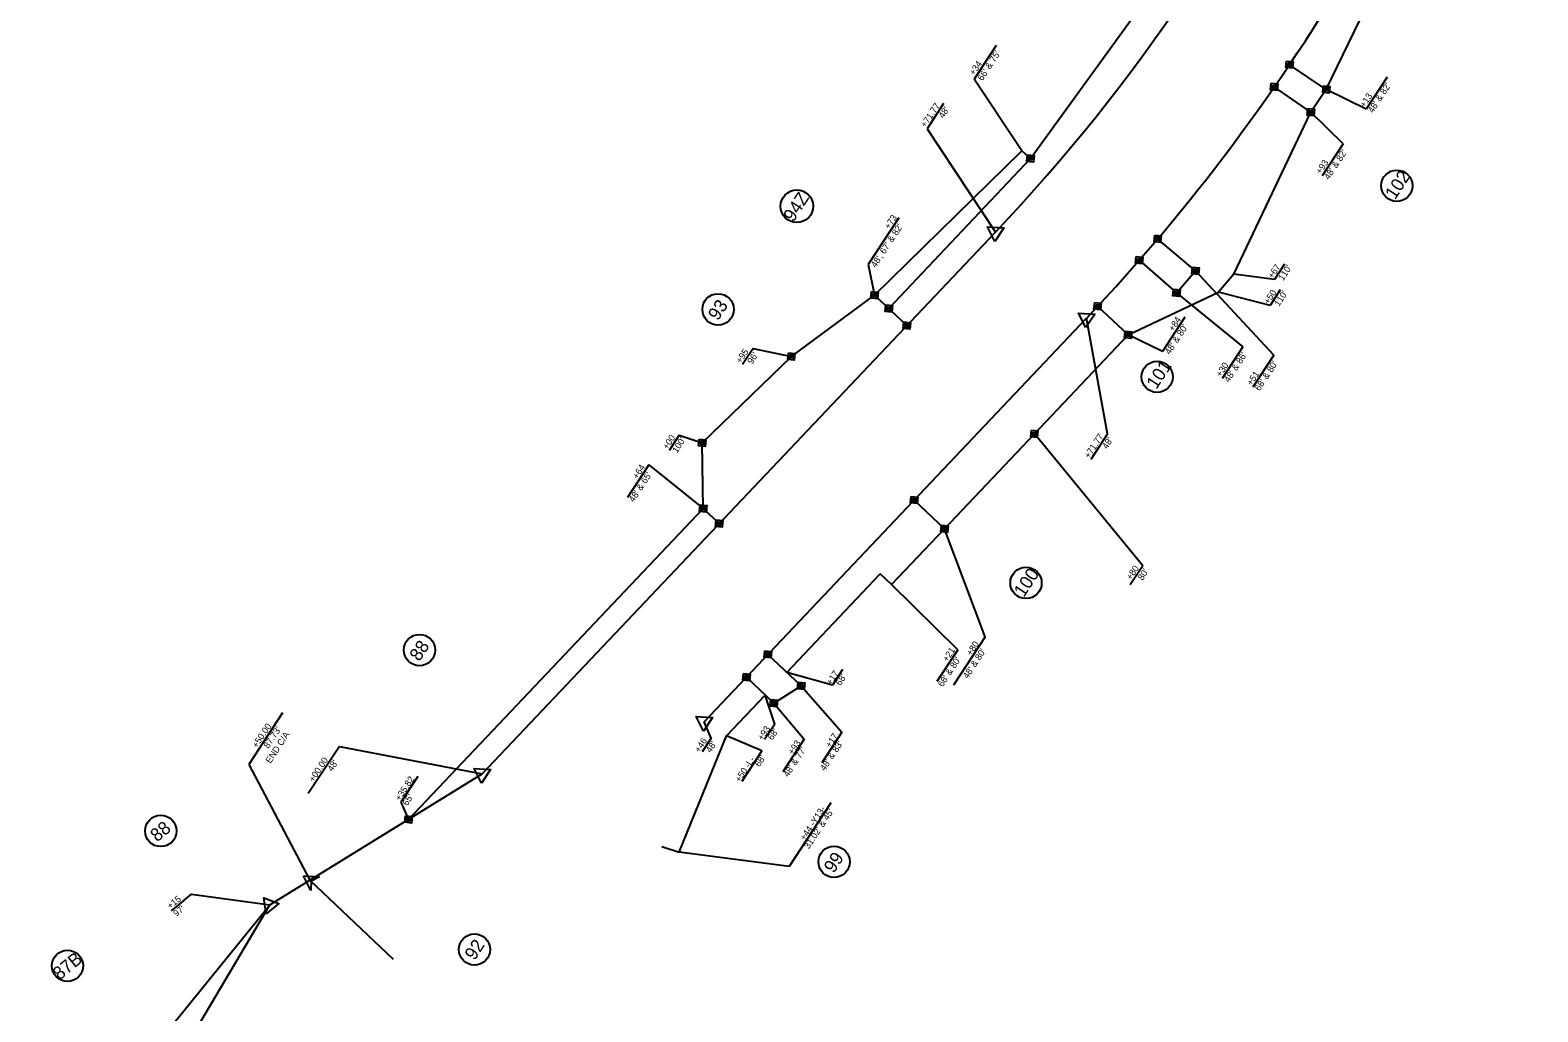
# Model space of a CAD drawing. Extents: x 2320946 to 2332748, y 597838 to 612698.
# Drawn here: x 2327264 to 2328420, y 602867 to 603619 of the extents above; entities that cross this region are included whole.
import ezdxf

# ---------------------------------------------------------------- set-up
doc = ezdxf.new("R2010")
doc.units = 0
for name, color, linetype in [('Prop Easement Construction', 7, 'Continuous'), ('Prop Easement Construction Station Offsets', 7, 'Continuous'), ('Prop Easement Permanent Drainage', 7, 'Continuous'), ('Prop Easement Permanent Drainage Station Offsets', 7, 'Continuous'), ('Prop Easement Permanent Drainage Utility', 7, 'Continuous'), ('Prop Easement Permanent Utility', 7, 'Continuous'), ('Prop Easement Permanent Utility Station Offsets', 7, 'Continuous'), ('Prop Parcel Number CELL', 7, 'Continuous'), ('Prop ROW CA Lines', 7, 'Continuous'), ('Prop ROW Marker CELL', 7, 'Continuous'), ('Prop ROW Permanent Easement CELL', 7, 'Continuous'), ('Prop ROW RW CA Lines', 7, 'Continuous'), ('Prop ROW RW Lines', 7, 'Continuous'), ('Prop ROW Station Offsets', 7, 'Continuous')]:
    doc.layers.add(name, color=color, linetype=linetype)

msp = doc.modelspace()

# ---------------------------------------------------------------- linework, layer by layer
at = {"layer": 'Prop Easement Construction'}
for p, q in [((2328257.6, 603573.9), (2328309.4, 603680.4)), ((2328186.8, 603432.5), (2328245.7, 603556.4)), ((2327911.5, 603416.4), (2328024.2, 603526.9)), ((2328024.2, 603526.9), (2328031, 603521)), ((2328186.8, 603432.5), (2328175, 603418.5)), ((2328105.8, 603386), (2328175, 603418.5)), ((2327924.5, 603194.6), (2327965.1, 603237.4)), ((2327844.2, 603127.4), (2327915.8, 603202.9)), ((2327924.5, 603194.6), (2327915.8, 603202.9)), ((2327798.1, 603078.8), (2327827.7, 603110)), ((2327761.6, 602989.6), (2327798.1, 603078.8)), ((2327748.3, 602994), (2327761.6, 602989.6)), ((2327264.3, 602723.6), (2327447.9, 602949.2))]:
    msp.add_line(p, q, dxfattribs=at)
at = {"layer": 'Prop Easement Construction Station Offsets'}
for p, q in [((2328004.7, 603607.6), (2327987.8, 603581.8)), ((2328024.2, 603526.9), (2327987.8, 603581.8)), ((2328225.7, 603440), (2328217.9, 603428.2)), ((2328222.4, 603420.3), (2328214.7, 603408.5)), ((2327975.2, 603144.7), (2327924.5, 603194.6)), ((2327975.2, 603144.7), (2327959.1, 603120.3)), ((2327879.2, 603117.7), (2327844.2, 603127.4)), ((2327887, 603129.6), (2327879.2, 603117.7)), ((2327834.9, 603087.7), (2327827.7, 603110)), ((2327834.9, 603087.7), (2327827.1, 603075.9)), ((2327825.1, 603067.3), (2327798.1, 603078.8)), ((2327825.1, 603067.3), (2327809.7, 603043.9)), ((2327878, 603027.5), (2327846, 602978.8)), ((2327846, 602978.8), (2327761.6, 602989.6))]:
    msp.add_line(p, q, dxfattribs=at)
for points in [[(2328217.9, 603428.2), (2328186.8, 603432.5)], [(2328214.7, 603408.5), (2328175, 603418.5)]]:
    msp.add_lwpolyline(points, dxfattribs=at)
at = {"layer": 'Prop Easement Permanent Drainage'}
for p, q in [((2328105.8, 603386), (2328082.4, 603407.8)), ((2328033.9, 603310), (2328105.8, 603386)), ((2327965.1, 603237.4), (2328033.9, 603310)), ((2327965.1, 603237.4), (2327941.8, 603259.4))]:
    msp.add_line(p, q, dxfattribs=at)
at = {"layer": 'Prop Easement Permanent Drainage Station Offsets'}
for p, q in [((2327930.1, 603475.6), (2327906.5, 603439.8)), ((2327906.5, 603439.8), (2327911.5, 603416.4)), ((2328149.3, 603399.4), (2328132, 603373.1)), ((2328132, 603373.1), (2328105.8, 603386)), ((2327817.9, 603374.8), (2327810.2, 603363.1)), ((2327761.8, 603309), (2327754, 603297.2)), ((2328117.1, 603209), (2328033.9, 603310)), ((2327738.5, 603286.3), (2327722.1, 603261.4)), ((2327738.5, 603286.3), (2327780, 603253)), ((2327996.1, 603154.5), (2327965.1, 603237.4)), ((2328117.1, 603209), (2328107.4, 603194.3)), ((2327996.1, 603154.5), (2327971.9, 603117.6))]:
    msp.add_line(p, q, dxfattribs=at)
for points in [[(2327817.9, 603374.8), (2327818.3, 603375.5), (2327847.7, 603369.4)], [(2327761.8, 603309), (2327779.4, 603303.2)]]:
    msp.add_lwpolyline(points, dxfattribs=at)
at = {"layer": 'Prop Easement Permanent Drainage Utility'}
for p, q in [((2328031, 603521), (2328123.8, 603649.1)), ((2327922.4, 603406), (2328031, 603521)), ((2327847.7, 603369.4), (2327911.5, 603416.4)), ((2327911.5, 603416.4), (2327936.2, 603393)), ((2327779.4, 603303.2), (2327847.7, 603369.4)), ((2327780, 603253), (2327779.4, 603303.2)), ((2327780, 603253), (2327792.4, 603241.3))]:
    msp.add_line(p, q, dxfattribs=at)
at = {"layer": 'Prop Easement Permanent Utility'}
for p, q in [((2328257.6, 603573.9), (2328229.4, 603592.8)), ((2328245.7, 603556.4), (2328217.8, 603575.8)), ((2328257.6, 603573.9), (2328245.7, 603556.4)), ((2328157.4, 603434.9), (2328128.4, 603459.5)), ((2328114.3, 603443.1), (2328142.9, 603418.1)), ((2328142.9, 603418.1), (2328157.4, 603434.9)), ((2327554.2, 603014.8), (2327780, 603253)), ((2327855.1, 603117.1), (2327829.7, 603141.1)), ((2327834.2, 603103.8), (2327813.2, 603123.7)), ((2327834.2, 603103.8), (2327855.1, 603117.1))]:
    msp.add_line(p, q, dxfattribs=at)
at = {"layer": 'Prop Easement Permanent Utility Station Offsets'}
for p, q in [((2328304.2, 603583.3), (2328288.1, 603558.8)), ((2328288.1, 603558.8), (2328257.6, 603573.9)), ((2328270.6, 603532.3), (2328245.7, 603556.4)), ((2328270.6, 603532.3), (2328254.5, 603507.8)), ((2328217.5, 603370.4), (2328157.4, 603434.9)), ((2328142.9, 603418.1), (2328193.7, 603376.6)), ((2328193.7, 603376.6), (2328177.8, 603352.5)), ((2328217.5, 603370.4), (2328201.4, 603345.9)), ((2327855.1, 603117.1), (2327886.4, 603081.5)), ((2327834.2, 603103.8), (2327857.6, 603076.1)), ((2327857.6, 603076.1), (2327841.2, 603051.1)), ((2327886.4, 603081.5), (2327871, 603058.1)), ((2327561.5, 603047.7), (2327548.5, 603028))]:
    msp.add_line(p, q, dxfattribs=at)
msp.add_lwpolyline([(2327548.5, 603028), (2327554.2, 603014.8)], dxfattribs=at)
at = {"layer": 'Prop Parcel Number CELL'}
for p, q in [((2328311.7, 603500.1), (2328311.7, 603500.1)), ((2327851.9, 603484.4), (2327851.9, 603484.4)), ((2327791.5, 603405.4), (2327791.5, 603405.4)), ((2328128, 603353.7), (2328128, 603353.7)), ((2328027.5, 603195.9), (2328027.5, 603195.9)), ((2327562.7, 603144.5), (2327562.7, 603144.5)), ((2327364.4, 603005.9), (2327364.4, 603005.9)), ((2327880.4, 602982.3), (2327880.4, 602982.3)), ((2327604.8, 602915.1), (2327604.8, 602915.1)), ((2327292.9, 602902.6), (2327292.9, 602902.6))]:
    msp.add_line(p, q, dxfattribs=at)
for centre, radius in [((2328311.7, 603500.1), 12), ((2327851.9, 603484.4), 12.5), ((2327791.5, 603405.4), 12), ((2328128, 603353.7), 12), ((2328027.5, 603195.9), 12), ((2327562.7, 603144.5), 12), ((2327364.4, 603005.9), 12), ((2327880.4, 602982.3), 12), ((2327604.8, 602915.1), 12), ((2327292.9, 602902.6), 12)]:
    msp.add_circle(centre, radius, dxfattribs=at)
at = {"layer": 'Prop ROW CA Lines'}
msp.add_line((2327478.7, 602968.2), (2327542.4, 602907.8), dxfattribs=at)
at = {"layer": 'Prop ROW Marker CELL'}
for p, q in [((2328229.4, 603592.8), (2328229.4, 603592.8)), ((2328217.8, 603575.8), (2328217.8, 603575.8)), ((2328257.6, 603573.9), (2328257.6, 603573.9)), ((2328245.7, 603556.4), (2328245.7, 603556.4)), ((2328031, 603521), (2328031, 603521)), ((2328004.1, 603464.6), (2328004.1, 603464.6)), ((2328128.4, 603459.5), (2328128.4, 603459.5)), ((2328114.3, 603443.1), (2328114.3, 603443.1)), ((2328157.4, 603434.9), (2328157.4, 603434.9)), ((2327911.5, 603416.4), (2327911.5, 603416.4)), ((2328142.9, 603418.1), (2328142.9, 603418.1)), ((2327922.4, 603406), (2327922.4, 603406)), ((2328073.8, 603398.6), (2328073.8, 603398.6)), ((2328082.4, 603407.8), (2328082.4, 603407.8)), ((2327936.2, 603393), (2327936.2, 603393)), ((2328105.8, 603386), (2328105.8, 603386)), ((2327847.7, 603369.4), (2327847.7, 603369.4)), ((2328033.9, 603310), (2328033.9, 603310)), ((2327779.4, 603303.2), (2327779.4, 603303.2)), ((2327941.8, 603259.4), (2327941.8, 603259.4)), ((2327780, 603253), (2327780, 603253)), ((2327792.4, 603241.3), (2327792.4, 603241.3)), ((2327965.1, 603237.4), (2327965.1, 603237.4)), ((2327829.7, 603141.1), (2327829.7, 603141.1)), ((2327813.2, 603123.7), (2327813.2, 603123.7)), ((2327855.1, 603117.1), (2327855.1, 603117.1)), ((2327834.2, 603103.8), (2327834.2, 603103.8)), ((2327780.8, 603089.6), (2327780.8, 603089.6)), ((2327610.7, 603049.7), (2327610.7, 603049.7)), ((2327554.2, 603014.8), (2327554.2, 603014.8)), ((2327479.3, 602960.3), (2327473.7, 602971.5)), ((2327473.7, 602971.5), (2327486.1, 602970.8)), ((2327486.1, 602970.8), (2327479.7, 602967.5)), ((2327479.7, 602967.5), (2327479.3, 602960.3)), ((2327447.9, 602949.2), (2327447.9, 602949.2))]:
    msp.add_line(p, q, dxfattribs=at)
for points in [[(2328003.7, 603457.4), (2327998.1, 603468.6), (2328010.6, 603467.9)], [(2328073.3, 603391.4), (2328067.8, 603402.6), (2328080.2, 603401.8)], [(2327780.4, 603082.4), (2327774.8, 603093.6), (2327787.3, 603092.9)], [(2327610.3, 603042.5), (2327604.7, 603053.7), (2327617.2, 603053)], [(2327445.3, 602942.4), (2327443.3, 602954.8), (2327455, 602950.3)]]:
    msp.add_lwpolyline(points, close=True, dxfattribs=at)
at = {"layer": 'Prop ROW Permanent Easement CELL'}
for points in [[(2328227.2, 603595.6), (2328232.2, 603595.1), (2328231.7, 603590.1), (2328226.7, 603590.6)], [(2328228.3, 603594.2), (2328230.8, 603594), (2328230.6, 603591.4), (2328228, 603591.7)], [(2328215.5, 603578.6), (2328220.6, 603578.1), (2328220.1, 603573), (2328215, 603573.5)], [(2328216.6, 603577.2), (2328219.2, 603576.9), (2328218.9, 603574.4), (2328216.4, 603574.6)], [(2328255.4, 603576.6), (2328260.4, 603576.1), (2328259.9, 603571.1), (2328254.9, 603571.6)], [(2328256.5, 603575.3), (2328259, 603575), (2328258.8, 603572.5), (2328256.3, 603572.7)], [(2328243.5, 603559.2), (2328248.5, 603558.7), (2328248, 603553.6), (2328242.9, 603554.1)], [(2328244.6, 603557.8), (2328247.1, 603557.5), (2328246.9, 603555), (2328244.3, 603555.3)], [(2328028.7, 603523.8), (2328033.8, 603523.3), (2328033.3, 603518.2), (2328028.2, 603518.7)], [(2328029.8, 603522.4), (2328032.4, 603522.1), (2328032.1, 603519.6), (2328029.6, 603519.9)], [(2328126.2, 603462.3), (2328131.2, 603461.8), (2328130.7, 603456.7), (2328125.7, 603457.2)], [(2328127.3, 603460.9), (2328129.8, 603460.6), (2328129.6, 603458.1), (2328127, 603458.4)], [(2328112, 603445.9), (2328117.1, 603445.3), (2328116.6, 603440.3), (2328111.5, 603440.8)], [(2328113.1, 603444.5), (2328115.7, 603444.2), (2328115.4, 603441.7), (2328112.9, 603441.9)], [(2328155.1, 603437.7), (2328160.2, 603437.2), (2328159.7, 603432.1), (2328154.6, 603432.6)], [(2328156.3, 603436.3), (2328158.8, 603436), (2328158.5, 603433.5), (2328156, 603433.8)], [(2328140.6, 603420.8), (2328145.7, 603420.3), (2328145.2, 603415.3), (2328140.1, 603415.8)], [(2327909.2, 603419.1), (2327914.3, 603418.6), (2327913.8, 603413.6), (2327908.7, 603414.1)], [(2327910.3, 603417.8), (2327912.9, 603417.5), (2327912.6, 603415), (2327910.1, 603415.2)], [(2328080.2, 603410.6), (2328085.2, 603410.1), (2328084.7, 603405), (2328079.6, 603405.5)], [(2328081.3, 603409.2), (2328083.8, 603408.9), (2328083.6, 603406.4), (2328081, 603406.7)], [(2328141.7, 603419.4), (2328144.3, 603419.2), (2328144, 603416.7), (2328141.5, 603416.9)], [(2327920.1, 603408.8), (2327925.2, 603408.3), (2327924.6, 603403.3), (2327919.6, 603403.8)], [(2327921.2, 603407.4), (2327923.8, 603407.2), (2327923.5, 603404.6), (2327921, 603404.9)], [(2327933.9, 603395.8), (2327938.9, 603395.2), (2327938.4, 603390.2), (2327933.4, 603390.7)], [(2327935, 603394.4), (2327937.5, 603394.1), (2327937.3, 603391.6), (2327934.8, 603391.8)], [(2328103.6, 603388.8), (2328108.6, 603388.3), (2328108.1, 603383.2), (2328103, 603383.7)], [(2328104.7, 603387.4), (2328107.2, 603387.1), (2328107, 603384.6), (2328104.4, 603384.8)], [(2327845.4, 603372.2), (2327850.4, 603371.7), (2327849.9, 603366.6), (2327844.9, 603367.1)], [(2327846.5, 603370.8), (2327849, 603370.5), (2327848.8, 603368), (2327846.3, 603368.2)], [(2327777.1, 603306), (2327782.2, 603305.5), (2327781.7, 603300.4), (2327776.6, 603300.9)], [(2328031.6, 603312.8), (2328036.6, 603312.3), (2328036.1, 603307.2), (2328031.1, 603307.7)], [(2328032.7, 603311.4), (2328035.3, 603311.1), (2328035, 603308.6), (2328032.5, 603308.8)], [(2327778.3, 603304.6), (2327780.8, 603304.3), (2327780.5, 603301.8), (2327778, 603302.1)], [(2327939.6, 603262.2), (2327944.6, 603261.7), (2327944.1, 603256.6), (2327939, 603257.2)], [(2327940.7, 603260.8), (2327943.2, 603260.6), (2327943, 603258), (2327940.4, 603258.3)], [(2327777.7, 603255.8), (2327782.8, 603255.3), (2327782.3, 603250.2), (2327777.2, 603250.7)], [(2327778.9, 603254.4), (2327781.4, 603254.1), (2327781.2, 603251.6), (2327778.6, 603251.9)], [(2327790.1, 603244.1), (2327795.1, 603243.6), (2327794.6, 603238.5), (2327789.6, 603239)], [(2327791.2, 603242.7), (2327793.8, 603242.4), (2327793.5, 603239.9), (2327791, 603240.2)], [(2327962.8, 603240.2), (2327967.8, 603239.7), (2327967.3, 603234.6), (2327962.3, 603235.1)], [(2327963.9, 603238.8), (2327966.5, 603238.5), (2327966.2, 603236), (2327963.7, 603236.3)], [(2327827.4, 603143.9), (2327832.5, 603143.4), (2327832, 603138.4), (2327826.9, 603138.9)], [(2327828.5, 603142.5), (2327831.1, 603142.3), (2327830.8, 603139.7), (2327828.3, 603140)], [(2327810.9, 603126.5), (2327816, 603126), (2327815.5, 603120.9), (2327810.4, 603121.4)], [(2327812, 603125.1), (2327814.6, 603124.9), (2327814.3, 603122.3), (2327811.8, 603122.6)], [(2327852.8, 603119.8), (2327857.9, 603119.3), (2327857.4, 603114.3), (2327852.3, 603114.8)], [(2327853.9, 603118.5), (2327856.5, 603118.2), (2327856.2, 603115.7), (2327853.7, 603115.9)], [(2327831.9, 603106.6), (2327837, 603106), (2327836.5, 603101), (2327831.4, 603101.5)], [(2327833.1, 603105.2), (2327835.6, 603104.9), (2327835.4, 603102.4), (2327832.8, 603102.6)], [(2327551.9, 603017.6), (2327557, 603017.1), (2327556.5, 603012), (2327551.4, 603012.6)], [(2327553.1, 603016.2), (2327555.6, 603016), (2327555.4, 603013.4), (2327552.8, 603013.7)]]:
    msp.add_lwpolyline(points, close=True, dxfattribs=at)
at = {"layer": 'Prop ROW RW CA Lines'}
for p, q in [((2327447.9, 602949.2), (2327478.7, 602968.2)), ((2327335.5, 602759.4), (2327447.9, 602949.2))]:
    msp.add_line(p, q, dxfattribs=at)
at = {"layer": 'Prop ROW RW Lines'}
for p, q in [((2327610.7, 603049.7), (2328004.1, 603464.6)), ((2327780.8, 603089.6), (2328073.8, 603398.6)), ((2327478.7, 602968.2), (2327610.7, 603049.7))]:
    msp.add_line(p, q, dxfattribs=at)
for radius, end in [(1498, 343.0696), (1402, 335.6209)]:
    msp.add_arc((2326986.7, 604429.2), radius, 316.5265, end, dxfattribs=at)
at = {"layer": 'Prop ROW Station Offsets'}
for p, q in [((2327964.4, 603563), (2327951.8, 603543.8)), ((2327951.8, 603543.8), (2328004.1, 603464.6)), ((2328090, 603310), (2328077.1, 603290.3)), ((2327457.8, 603096.5), (2327431.8, 603056.9)), ((2327786.1, 603077), (2327779.2, 603066.4)), ((2327501.3, 603070.7), (2327477.5, 603034.5)), ((2327382.4, 602952.9), (2327372.5, 602944.8))]:
    msp.add_line(p, q, dxfattribs=at)
for points in [[(2328090, 603310), (2328073.8, 603398.6)], [(2327786.1, 603077), (2327780.8, 603089.6)], [(2327501.3, 603070.7), (2327610.7, 603049.7)], [(2327431.8, 603056.9), (2327478.7, 602968.2)], [(2327382.4, 602952.9), (2327387.9, 602957.4), (2327447.9, 602949.2)]]:
    msp.add_lwpolyline(points, dxfattribs=at)

# ---------------------------------------------------------------- texts
at = {"layer": 'Prop Easement Construction Station Offsets'}
for s, p in [('+34', (2327987.8, 603584.2)), ("66' & 75'", (2327994.1, 603580.1)), ('+67', (2328216.6, 603428.5)), ("110'", (2328224.6, 603427)), ('+50', (2328213.5, 603408.9)), ("110'", (2328221.4, 603407.3)), ('+21', (2327967.3, 603135)), ("68' & 80'", (2327963.7, 603115.8)), ('+17', (2327878.1, 603117.2)), ("68'", (2327885.3, 603116.8)), ('+93', (2327825.6, 603074.8)), ("68'", (2327833.2, 603075)), ("68'", (2327823.4, 603054.5)), ('+50 -L-', (2327808.2, 603042.8)), ('+44 -Y13-', (2327858, 602998.2)), ("31.02' & 45'", (2327861.2, 602991.7))]:
    msp.add_text(s, height=5, rotation=56.6615, dxfattribs=at).set_placement(p)
at = {"layer": 'Prop Easement Permanent Drainage Station Offsets'}
for s, p in [("48', 67' & 82'", (2327912.4, 603437)), ('+73', (2327922.7, 603466.3)), ('+84', (2328140.4, 603388.2)), ("48' & 80'", (2328137.7, 603370.4)), ('+95', (2327809, 603363.6)), ("96'", (2327817.7, 603363.1)), ('+00', (2327752.8, 603297.7)), ("100'", (2327760.1, 603295)), ('+64', (2327729.7, 603275.1)), ("48' & 65'", (2327726.9, 603257.3)), ('+80', (2328108.1, 603197.7)), ("80'", (2328116.9, 603197.4)), ("48' & 80'", (2327982.9, 603122.1)), ('+80', (2327985.5, 603139.7))]:
    msp.add_text(s, height=5, rotation=56.6615, dxfattribs=at).set_placement(p)
at = {"layer": 'Prop Easement Permanent Utility Station Offsets'}
for s, rotation, p in [('+13', 56.6615, (2328287, 603559.5)), ("48' & 82'", 56.6615, (2328293.3, 603555.4)), ("48' & 82'", 56.6615, (2328259.7, 603504.3)), ('+93', 56.6615, (2328253.4, 603508.5)), ('+30', 56.6615, (2328176.8, 603353.2)), ("48' & 86'", 56.6615, (2328183, 603349.1)), ("68' & 80'", 56.6615, (2328206.6, 603342.5)), ('+51', 56.6615, (2328200.4, 603346.6)), ('+93', 56.6615, (2327848.9, 603063.9)), ("48' & 83'", 56.6615, (2327873.4, 603051.5)), ('+17', 56.6615, (2327877.5, 603069.2)), ("48' & 77'", 56.6615, (2327845.2, 603046.8)), ('+35.82', 56.6599, (2327547.7, 603028.5)), ("65'", 56.6599, (2327553.4, 603024.8))]:
    msp.add_text(s, height=5, rotation=rotation, dxfattribs=at).set_placement(p)
at = {"layer": 'Prop Parcel Number CELL'}
for s, rotation, p in [('102', 56.6599, (2328310.3, 603488.9)), ('94Z', 56.6599, (2327849.1, 603471.7)), ('93', 56.6599, (2327791.4, 603396.2)), ('101', 56.6599, (2328127.4, 603343.7)), ('100', 56.6599, (2328025.8, 603184.3)), ('88', 56.6599, (2327562.6, 603135.2)), ('88', 39.228, (2327361.5, 602997.1)), ('99', 56.6599, (2327880.2, 602973)), ('87B', 39.228, (2327286.8, 602891.2)), ('92', 56.6599, (2327604.9, 602906.2))]:
    msp.add_text(s, height=10, rotation=rotation, dxfattribs=at).set_placement(p)
at = {"layer": 'Prop ROW Station Offsets'}
for s, rotation, p in [('+71.77', 56.6615, (2327950.5, 603544.2)), ("48' ", 56.6615, (2327964.2, 603551.3)), ('+71.77', 56.6615, (2328075.9, 603290.8)), ("48'", 56.6615, (2328089.6, 603298)), ('+50.00', 56.6615, (2327438.2, 603069)), ("87.73'", 56.6615, (2327447, 603068.7)), ('END C/A', 56.6615, (2327448.5, 603057.2)), ('+46', 56.6599, (2327777.2, 603065.6)), ("48'", 56.6599, (2327785.9, 603065.3)), ('+00.00', 56.6615, (2327481.6, 603043)), ("48'", 56.6615, (2327495.8, 603051)), ('+15', 39.228, (2327371.7, 602945.8)), ("97'", 39.228, (2327376.5, 602940))]:
    msp.add_text(s, height=5, rotation=rotation, dxfattribs=at).set_placement(p)

doc.saveas('drawing.dxf')
